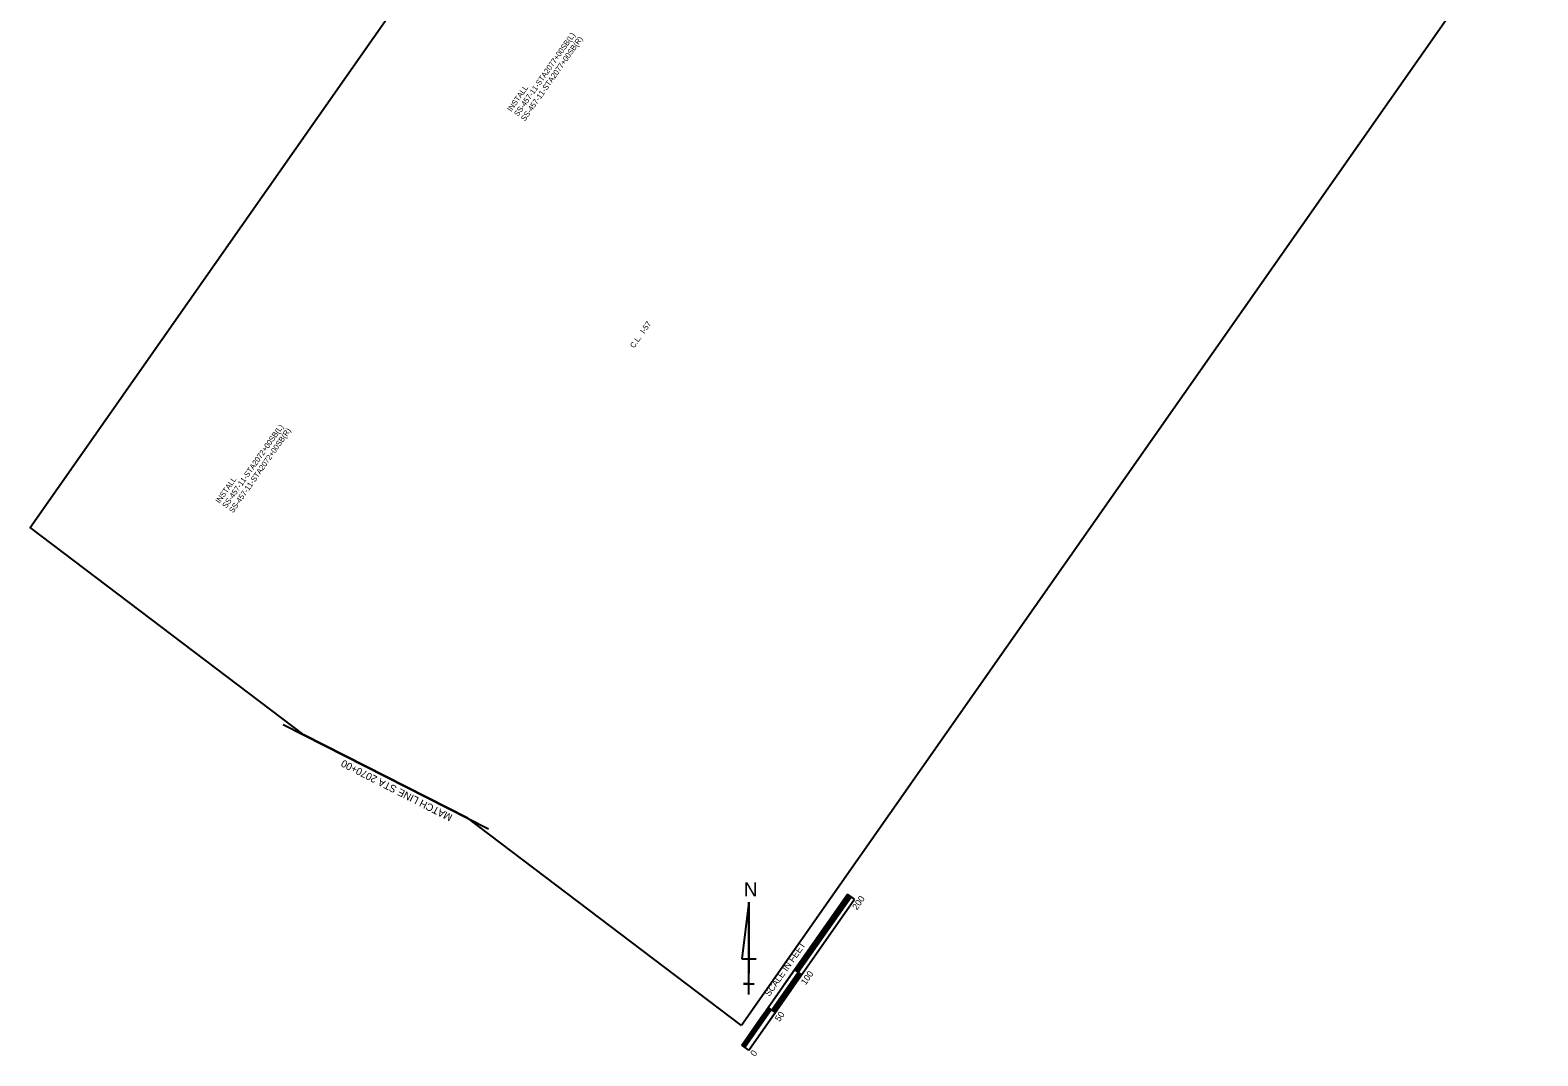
# Model space of a CAD drawing. Extents: x 1713635 to 1715321, y 763653 to 765849.
# Drawn here: x 1713635 to 1715271, y 763653 to 764767 of the extents above; entities that cross this region are included whole.
import ezdxf

# ---------------------------------------------------------------- set-up
doc = ezdxf.new("R2010")
doc.units = 0
for name, color, linetype in [('R_6IN_DASHED-RPM_WHITE_ENHANCED THERMO', 7, 'Continuous'), ('R_6IN_DBL_YELLOW_REFLECTORIZED_PAINT', 7, 'Continuous'), ('R_6IN_SOLID_WHITE_THERMOPLASTIC', 7, 'Continuous'), ('R_PM_DOTTED_LINE', 7, 'Continuous'), ('R_RPM_TYPE 2_RED-WHITE', 7, 'Continuous'), ('R_WORDS_WHITE_THERMO', 7, 'Continuous')]:
    doc.layers.add(name, color=color, linetype=linetype)

msp = doc.modelspace()

# ---------------------------------------------------------------- linework, layer by layer
at = {"layer": 'R_6IN_DBL_YELLOW_REFLECTORIZED_PAINT'}
msp.add_line((1713909.8, 764013), (1714132.7, 763899.7), dxfattribs=at)
at = {"layer": 'R_PM_DOTTED_LINE'}
for p, q in [((1714415.3, 763819.8), (1714407.6, 763758.3)), ((1714415.3, 763719.8), (1714415.3, 763819.8)), ((1714415.3, 763819.8), (1714415.3, 763742.9)), ((1714407.6, 763758.3), (1714423, 763758.3)), ((1714415.3, 763719.8), (1714415.3, 763742.9)), ((1714415.3, 763731.3), (1714409.5, 763731.3)), ((1714409.5, 763731.3), (1714421.1, 763731.3)), ((1714415.3, 763719.8), (1714415.3, 763731.3))]:
    msp.add_line(p, q, dxfattribs=at)
at = {"layer": 'R_RPM_TYPE 2_RED-WHITE'}
msp.add_lwpolyline([(1714407.2, 763686.1), (1714110.4, 763911), (1713932.1, 764001.6), (1713635.3, 764226.6), (1714321.9, 765207.1), (1714362.4, 765178.7), (1714460.4, 765318.6), (1714569, 765303.7), (1714877.6, 765203.8), (1715007.6, 765051.8), (1715271.4, 764920.3)], close=True, dxfattribs=at)
at = {"layer": 'R_WORDS_WHITE_THERMO'}
for p, q in [((1714415.3, 763659.3), (1714530, 763823.1)), ((1714453.3, 763730.3), (1714522.1, 763828.6)), ((1714465.4, 763746.2), (1714522.8, 763828.2)), ((1714466.1, 763745.8), (1714523.4, 763827.7)), ((1714466.7, 763745.3), (1714524.1, 763827.2)), ((1714467.4, 763744.9), (1714524.7, 763826.8)), ((1714468, 763744.4), (1714525.4, 763826.3)), ((1714468.7, 763743.9), (1714526.1, 763825.9)), ((1714530, 763823.1), (1714522.1, 763828.6)), ((1714407.4, 763664.8), (1714499.2, 763795.8)), ((1714468.7, 763743.9), (1714503.1, 763793.1)), ((1714440, 763703), (1714468.7, 763743.9)), ((1714440.7, 763702.5), (1714469.4, 763743.5)), ((1714441.3, 763702.1), (1714470, 763743)), ((1714442, 763701.6), (1714470.7, 763742.6)), ((1714442.6, 763701.1), (1714471.3, 763742.1)), ((1714443.3, 763700.7), (1714472, 763741.6)), ((1714472.6, 763741.2), (1714464.8, 763746.7)), ((1714438.2, 763692), (1714461.2, 763724.8)), ((1714407.4, 763664.8), (1714430.3, 763697.5)), ((1714408.1, 763664.3), (1714436.7, 763705.3)), ((1714408.7, 763663.9), (1714437.4, 763704.8)), ((1714409.4, 763663.4), (1714438.1, 763704.4)), ((1714410, 763662.9), (1714438.7, 763703.9)), ((1714410.7, 763662.5), (1714439.4, 763703.4)), ((1714444, 763700.2), (1714436.1, 763705.7)), ((1714415.3, 763659.3), (1714407.4, 763664.8))]:
    msp.add_line(p, q, dxfattribs=at)

# ---------------------------------------------------------------- texts
at = {"layer": 'R_6IN_DASHED-RPM_WHITE_ENHANCED THERMO'}
msp.add_text('C.L.  I-57', height=6, rotation=54.8523, dxfattribs=at).set_placement((1714290.6, 764421))
at = {"layer": 'R_6IN_DBL_YELLOW_REFLECTORIZED_PAINT'}
msp.add_text('MATCH LINE STA 2070+00', height=8, rotation=153.0652, dxfattribs=at).set_placement((1714094.3, 763914.5))
at = {"layer": 'R_6IN_SOLID_WHITE_THERMOPLASTIC'}
for s, p in [('SS-457-11-STA2077+00SB(L)', (1714164.8, 764672.6)), ('SS-457-11-STA2077+00SB(R)', (1714172.2, 764667.4)), ('INSTALL', (1714157.4, 764677.7)), ('SS-457-11-STA2072+00SB(L)', (1713848.2, 764247.2)), ('SS-457-11-STA2072+00SB(R)', (1713855.6, 764242.1)), ('INSTALL', (1713840.8, 764252.4))]:
    msp.add_text(s, height=6, rotation=55, dxfattribs=at).set_placement(p)
at = {"layer": 'R_PM_DOTTED_LINE'}
msp.add_text('N', height=15.4, rotation=360, dxfattribs=at).set_placement((1714409.7, 763826.2))
at = {"layer": 'R_WORDS_WHITE_THERMO'}
for s, height, p in [('200', 7, (1714532.5, 763810.9)), ('SCALE IN FEET', 7.001, (1714437.5, 763716.9)), ('100', 7, (1714476.8, 763729.4)), ('50', 7, (1714448.5, 763689.6)), ('0', 7, (1714421.8, 763651.9))]:
    msp.add_text(s, height=height, rotation=55.0003, dxfattribs=at).set_placement(p)

doc.saveas('drawing.dxf')
